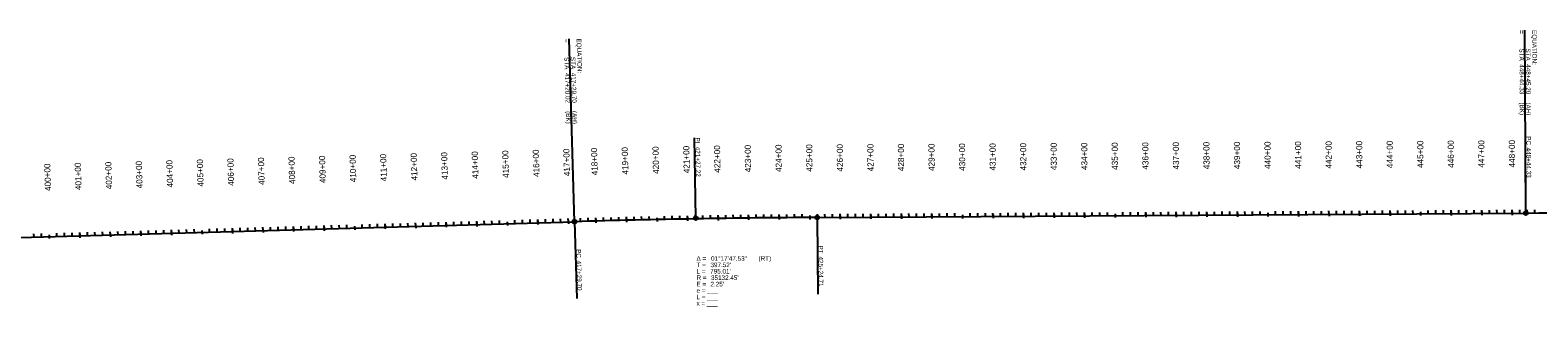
# Model space of a CAD drawing. Extents: x 22693007 to 22771804, y 6223023 to 6251673.
# Drawn here: x 22717627 to 22722562, y 6235486 to 6236393 of the extents above; entities that cross this region are included whole.
import ezdxf

# ---------------------------------------------------------------- set-up
doc = ezdxf.new("R2010")
doc.units = 0
for name, color, linetype in [('Default', 7, 'Continuous'), ('Draft_2', 7, 'Continuous'), ('NamedBoundary', 7, 'Continuous'), ('SheetBorder', 7, 'Continuous'), ('TextAlignment', 7, 'Continuous')]:
    doc.layers.add(name, color=color, linetype=linetype)

msp = doc.modelspace()

# ---------------------------------------------------------------- linework, layer by layer
at = {"layer": 'Default'}
for p, q in [((22720203.3, 6235778.9), (22722522.9, 6235793)), ((22714843.8, 6235633.8), (22719408.5, 6235765)), ((22714843.8, 6235633.8), (22719408.5, 6235765))]:
    msp.add_line(p, q, dxfattribs=at)
for centre, radius, start, end in [((22722417.6, 6253010.9), 17218.1, 270.3503, 272.59113), ((22720418.1, 6200647.1), 35132.4, 90.3503, 91.64684)]:
    msp.add_arc(centre, radius, start, end, dxfattribs=at)
at = {"layer": 'Draft_2'}
for p, q in [((22720778.6, 6235782.4), (22720778.5, 6235793.3)), ((22720878.6, 6235783), (22720878.5, 6235793.9)), ((22720978.6, 6235783.6), (22720978.5, 6235794.5)), ((22721078.6, 6235784.2), (22721078.5, 6235795.1)), ((22721278.6, 6235785.4), (22721278.5, 6235796.3)), ((22721378.6, 6235786), (22721378.5, 6235797)), ((22721478.6, 6235786.6), (22721478.5, 6235797.6)), ((22721578.6, 6235787.3), (22721578.5, 6235798.2)), ((22721678.6, 6235794), (22721678.6, 6235781.8)), ((22721778.6, 6235788.5), (22721778.5, 6235799.4)), ((22721878.6, 6235789.1), (22721878.5, 6235800)), ((22721978.6, 6235789.7), (22721978.5, 6235800.6)), ((22722078.6, 6235790.3), (22722078.5, 6235801.2)), ((22722178.5, 6235797), (22722178.6, 6235784.8)), ((22722278.6, 6235791.5), (22722278.5, 6235802.5)), ((22722378.6, 6235792.2), (22722378.5, 6235803.1)), ((22722478.6, 6235792.8), (22722478.5, 6235803.7)), ((22718288.9, 6235732.8), (22718288.6, 6235743.7)), ((22718388.9, 6235735.7), (22718388.5, 6235746.6)), ((22718488.8, 6235738.6), (22718488.5, 6235749.5)), ((22718588.8, 6235741.4), (22718588.5, 6235752.3)), ((22718688.6, 6235750.4), (22718688.9, 6235738.2)), ((22718788.7, 6235747.2), (22718788.4, 6235758.1)), ((22718888.7, 6235750.1), (22718888.3, 6235761)), ((22718988.6, 6235752.9), (22718988.3, 6235763.8)), ((22719088.6, 6235755.8), (22719088.3, 6235766.7)), ((22719188.4, 6235764.8), (22719188.7, 6235752.6)), ((22719288.5, 6235761.5), (22719288.2, 6235772.5)), ((22719388.4, 6235764.4), (22719388.1, 6235775.3)), ((22719478.7, 6235766.9), (22719478.4, 6235777.9)), ((22719578.7, 6235769.5), (22719578.4, 6235780.4)), ((22719678.5, 6235777.8), (22719678.8, 6235765.6)), ((22719778.7, 6235773.7), (22719778.5, 6235784.6)), ((22719878.6, 6235775.4), (22719878.5, 6235786.3)), ((22719978.6, 6235776.8), (22719978.5, 6235787.7)), ((22720078.6, 6235777.9), (22720078.5, 6235788.8)), ((22720178.6, 6235784.8), (22720178.7, 6235772.6)), ((22720278.6, 6235779.3), (22720278.5, 6235790.2)), ((22720378.6, 6235779.9), (22720378.5, 6235790.8)), ((22720478.6, 6235780.5), (22720478.5, 6235791.5)), ((22720578.6, 6235781.1), (22720578.5, 6235792.1)), ((22720678.6, 6235787.9), (22720678.6, 6235775.6)), ((22721178.6, 6235790.9), (22721178.6, 6235778.7)), ((22717689, 6235721.7), (22717689.3, 6235709.4)), ((22717789.1, 6235718.4), (22717788.8, 6235729.4)), ((22717889.1, 6235721.3), (22717888.8, 6235732.2)), ((22717989, 6235724.2), (22717988.7, 6235735.1)), ((22718089, 6235727.1), (22718088.7, 6235738)), ((22718188.8, 6235736.1), (22718189.1, 6235723.8))]:
    msp.add_line(p, q, dxfattribs=at)
at = {"layer": 'NamedBoundary'}
for p, q in [((22720203.3, 6235778.9), (22722522.9, 6235793)), ((22714843.8, 6235633.8), (22719408.5, 6235765))]:
    msp.add_line(p, q, dxfattribs=at)
for centre, radius, start, end in [((22722417.6, 6253010.9), 17218.1, 270.3503, 272.59113), ((22720418.1, 6200647.1), 35132.4, 90.3503, 91.64684)]:
    msp.add_arc(centre, radius, start, end, dxfattribs=at)
at = {"layer": 'SheetBorder'}
for p, q in [((22720628.6, 6235781.5), (22720628.5, 6235792.4)), ((22720653.6, 6235781.6), (22720653.5, 6235792.5)), ((22720703.6, 6235781.9), (22720703.5, 6235792.8)), ((22720728.6, 6235782.1), (22720728.5, 6235793)), ((22720753.6, 6235782.2), (22720753.5, 6235793.1)), ((22720803.6, 6235782.5), (22720803.5, 6235793.4)), ((22720828.6, 6235782.7), (22720828.5, 6235793.6)), ((22720853.6, 6235782.8), (22720853.5, 6235793.7)), ((22720903.6, 6235783.1), (22720903.5, 6235794.1)), ((22720928.6, 6235783.3), (22720928.5, 6235794.2)), ((22720953.6, 6235783.4), (22720953.5, 6235794.4)), ((22721003.6, 6235783.7), (22721003.5, 6235794.7)), ((22721028.6, 6235783.9), (22721028.5, 6235794.8)), ((22721053.6, 6235784.1), (22721053.5, 6235795)), ((22721103.6, 6235784.4), (22721103.5, 6235795.3)), ((22721128.6, 6235784.5), (22721128.5, 6235795.4)), ((22721153.6, 6235784.7), (22721153.5, 6235795.6)), ((22721203.6, 6235785), (22721203.5, 6235795.9)), ((22721228.6, 6235785.1), (22721228.5, 6235796)), ((22721253.6, 6235785.3), (22721253.5, 6235796.2)), ((22721303.6, 6235785.6), (22721303.5, 6235796.5)), ((22721328.6, 6235785.7), (22721328.5, 6235796.7)), ((22721353.6, 6235785.9), (22721353.5, 6235796.8)), ((22721403.6, 6235786.2), (22721403.5, 6235797.1)), ((22721428.6, 6235786.3), (22721428.5, 6235797.3)), ((22721453.6, 6235786.5), (22721453.5, 6235797.4)), ((22721478.6, 6235792.8), (22721478.6, 6235780.5)), ((22721503.6, 6235786.8), (22721503.5, 6235797.7)), ((22721528.6, 6235787), (22721528.5, 6235797.9)), ((22721553.6, 6235787.1), (22721553.5, 6235798)), ((22721578.6, 6235793.4), (22721578.6, 6235781.1)), ((22721603.6, 6235787.4), (22721603.5, 6235798.3)), ((22721628.6, 6235787.6), (22721628.5, 6235798.5)), ((22721653.6, 6235787.7), (22721653.5, 6235798.6)), ((22721678.6, 6235794), (22721678.6, 6235781.8)), ((22721703.6, 6235788), (22721703.5, 6235798.9)), ((22721728.6, 6235788.2), (22721728.5, 6235799.1)), ((22721753.6, 6235788.3), (22721753.5, 6235799.2)), ((22721778.6, 6235794.6), (22721778.6, 6235782.4)), ((22721803.6, 6235788.6), (22721803.5, 6235799.6)), ((22721828.6, 6235788.8), (22721828.5, 6235799.7)), ((22721853.6, 6235788.9), (22721853.5, 6235799.9)), ((22721878.5, 6235795.2), (22721878.6, 6235783)), ((22721903.6, 6235789.2), (22721903.5, 6235800.2)), ((22721928.6, 6235789.4), (22721928.5, 6235800.3)), ((22721953.6, 6235789.6), (22721953.5, 6235800.5)), ((22721978.5, 6235795.8), (22721978.6, 6235783.6)), ((22722003.6, 6235789.9), (22722003.5, 6235800.8)), ((22722028.6, 6235790), (22722028.5, 6235800.9)), ((22722053.6, 6235790.2), (22722053.5, 6235801.1)), ((22722078.5, 6235796.4), (22722078.6, 6235784.2)), ((22722103.6, 6235790.5), (22722103.5, 6235801.4)), ((22722128.6, 6235790.6), (22722128.5, 6235801.5)), ((22722153.6, 6235790.8), (22722153.5, 6235801.7)), ((22722178.5, 6235797), (22722178.6, 6235784.8)), ((22722203.6, 6235791.1), (22722203.5, 6235802)), ((22722228.6, 6235791.2), (22722228.5, 6235802.2)), ((22722253.6, 6235791.4), (22722253.5, 6235802.3)), ((22722278.5, 6235797.7), (22722278.6, 6235785.4)), ((22722303.6, 6235791.7), (22722303.5, 6235802.6)), ((22722328.6, 6235791.8), (22722328.5, 6235802.8)), ((22722353.6, 6235792), (22722353.5, 6235802.9)), ((22722378.5, 6235798.3), (22722378.6, 6235786)), ((22722403.6, 6235792.3), (22722403.5, 6235803.2)), ((22722428.6, 6235792.5), (22722428.5, 6235803.4)), ((22722453.6, 6235792.6), (22722453.5, 6235803.5)), ((22722478.5, 6235798.9), (22722478.6, 6235786.6)), ((22722503.6, 6235792.9), (22722503.5, 6235803.8)), ((22722527.7, 6235793.1), (22722527.6, 6235804)), ((22722552.7, 6235793.2), (22722552.6, 6235804.2)), ((22718263.9, 6235732.1), (22718263.6, 6235743)), ((22718313.9, 6235733.5), (22718313.6, 6235744.4)), ((22718338.9, 6235734.2), (22718338.6, 6235745.2)), ((22718363.9, 6235735), (22718363.6, 6235745.9)), ((22718413.8, 6235736.4), (22718413.5, 6235747.3)), ((22718438.8, 6235737.1), (22718438.5, 6235748)), ((22718463.8, 6235737.8), (22718463.5, 6235748.8)), ((22718488.6, 6235744.7), (22718489, 6235732.4)), ((22718513.8, 6235739.3), (22718513.5, 6235750.2)), ((22718538.8, 6235740), (22718538.5, 6235750.9)), ((22718563.8, 6235740.7), (22718563.5, 6235751.6)), ((22718588.6, 6235747.5), (22718589, 6235735.3)), ((22718613.8, 6235742.1), (22718613.5, 6235753.1)), ((22718638.8, 6235742.9), (22718638.4, 6235753.8)), ((22718663.7, 6235743.6), (22718663.4, 6235754.5)), ((22718688.6, 6235750.4), (22718688.9, 6235738.2)), ((22718713.7, 6235745), (22718713.4, 6235755.9)), ((22718738.7, 6235745.7), (22718738.4, 6235756.7)), ((22718763.7, 6235746.5), (22718763.4, 6235757.4)), ((22718788.5, 6235753.3), (22718788.9, 6235741.1)), ((22718813.7, 6235747.9), (22718813.4, 6235758.8)), ((22718838.7, 6235748.6), (22718838.4, 6235759.5)), ((22718863.7, 6235749.3), (22718863.3, 6235760.2)), ((22718888.5, 6235756.2), (22718888.8, 6235743.9)), ((22718913.6, 6235750.8), (22718913.3, 6235761.7)), ((22718938.6, 6235751.5), (22718938.3, 6235762.4)), ((22718963.6, 6235752.2), (22718963.3, 6235763.1)), ((22718988.4, 6235759), (22718988.8, 6235746.8)), ((22719013.6, 6235753.6), (22719013.3, 6235764.6)), ((22719038.6, 6235754.4), (22719038.3, 6235765.3)), ((22719063.6, 6235755.1), (22719063.3, 6235766)), ((22719088.4, 6235761.9), (22719088.7, 6235749.7)), ((22719113.6, 6235756.5), (22719113.2, 6235767.4)), ((22719138.5, 6235757.2), (22719138.2, 6235768.2)), ((22719163.5, 6235758), (22719163.2, 6235768.9)), ((22719188.4, 6235764.8), (22719188.7, 6235752.6)), ((22719213.5, 6235759.4), (22719213.2, 6235770.3)), ((22719238.5, 6235760.1), (22719238.2, 6235771)), ((22719263.5, 6235760.8), (22719263.2, 6235771.7)), ((22719288.3, 6235767.7), (22719288.7, 6235755.4)), ((22719313.5, 6235762.3), (22719313.2, 6235773.2)), ((22719338.5, 6235763), (22719338.2, 6235773.9)), ((22719363.5, 6235763.7), (22719363.1, 6235774.6)), ((22719388.3, 6235770.5), (22719388.6, 6235758.3)), ((22719428.7, 6235765.6), (22719428.4, 6235776.5)), ((22719453.7, 6235766.3), (22719453.4, 6235777.2)), ((22719478.6, 6235773.1), (22719478.9, 6235760.8)), ((22719503.7, 6235767.6), (22719503.4, 6235778.5)), ((22719528.7, 6235768.2), (22719528.4, 6235779.2)), ((22719553.7, 6235768.9), (22719553.4, 6235779.8)), ((22719578.5, 6235775.6), (22719578.8, 6235763.4)), ((22719603.7, 6235770.1), (22719603.4, 6235781)), ((22719628.7, 6235770.6), (22719628.4, 6235781.6)), ((22719653.7, 6235771.2), (22719653.4, 6235782.1)), ((22719678.5, 6235777.8), (22719678.8, 6235765.6)), ((22719703.7, 6235772.2), (22719703.4, 6235783.2)), ((22719728.7, 6235772.7), (22719728.4, 6235783.7)), ((22719753.7, 6235773.2), (22719753.4, 6235784.1)), ((22719778.5, 6235779.8), (22719778.8, 6235767.6)), ((22719803.6, 6235774.1), (22719803.5, 6235785.1)), ((22719828.6, 6235774.6), (22719828.5, 6235785.5)), ((22719853.6, 6235775), (22719853.5, 6235785.9)), ((22719878.5, 6235781.5), (22719878.7, 6235769.2)), ((22719903.6, 6235775.7), (22719903.5, 6235786.7)), ((22719928.6, 6235776.1), (22719928.5, 6235787)), ((22719953.6, 6235776.4), (22719953.5, 6235787.4)), ((22719978.6, 6235782.9), (22719978.7, 6235770.6)), ((22720003.6, 6235777.1), (22720003.5, 6235788)), ((22720028.6, 6235777.3), (22720028.5, 6235788.3)), ((22720053.6, 6235777.6), (22720053.5, 6235788.5)), ((22720078.6, 6235784), (22720078.7, 6235771.7)), ((22720103.6, 6235778.1), (22720103.5, 6235789)), ((22720128.6, 6235778.3), (22720128.5, 6235789.2)), ((22720153.6, 6235778.5), (22720153.5, 6235789.4)), ((22720178.6, 6235784.8), (22720178.7, 6235772.6)), ((22720203.6, 6235778.9), (22720203.6, 6235789.8)), ((22720228.6, 6235779), (22720228.5, 6235789.9)), ((22720253.6, 6235779.2), (22720253.5, 6235790.1)), ((22720278.6, 6235785.4), (22720278.7, 6235773.2)), ((22720303.6, 6235779.5), (22720303.5, 6235790.4)), ((22720328.6, 6235779.6), (22720328.5, 6235790.5)), ((22720353.6, 6235779.8), (22720353.5, 6235790.7)), ((22720378.6, 6235786), (22720378.7, 6235773.8)), ((22720403.6, 6235780.1), (22720403.5, 6235791)), ((22720428.6, 6235780.2), (22720428.5, 6235791.1)), ((22720453.6, 6235780.4), (22720453.5, 6235791.3)), ((22720478.6, 6235786.7), (22720478.6, 6235774.4)), ((22720503.6, 6235780.7), (22720503.5, 6235791.6)), ((22720528.6, 6235780.8), (22720528.5, 6235791.8)), ((22720553.6, 6235781), (22720553.5, 6235791.9)), ((22720578.6, 6235787.3), (22720578.6, 6235775)), ((22720603.6, 6235781.3), (22720603.5, 6235792.2)), ((22720678.6, 6235787.9), (22720678.6, 6235775.6)), ((22720778.6, 6235788.5), (22720778.6, 6235776.2)), ((22720878.6, 6235789.1), (22720878.6, 6235776.9)), ((22720978.6, 6235789.7), (22720978.6, 6235777.5)), ((22721078.6, 6235790.3), (22721078.6, 6235778.1)), ((22721178.6, 6235790.9), (22721178.6, 6235778.7)), ((22721278.6, 6235791.5), (22721278.6, 6235779.3)), ((22721378.6, 6235792.2), (22721378.6, 6235779.9)), ((22717639.2, 6235714.1), (22717638.9, 6235725)), ((22717664.2, 6235714.8), (22717663.8, 6235725.8)), ((22717689, 6235721.7), (22717689.3, 6235709.4)), ((22717714.1, 6235716.3), (22717713.8, 6235727.2)), ((22717739.1, 6235717), (22717738.8, 6235727.9)), ((22717764.1, 6235717.7), (22717763.8, 6235728.6)), ((22717788.9, 6235724.6), (22717789.3, 6235712.3)), ((22717814.1, 6235719.2), (22717813.8, 6235730.1)), ((22717839.1, 6235719.9), (22717838.8, 6235730.8)), ((22717864.1, 6235720.6), (22717863.8, 6235731.5)), ((22717888.9, 6235727.4), (22717889.2, 6235715.2)), ((22717914.1, 6235722), (22717913.7, 6235732.9)), ((22717939, 6235722.8), (22717938.7, 6235733.7)), ((22717964, 6235723.5), (22717963.7, 6235734.4)), ((22717988.8, 6235730.3), (22717989.2, 6235718.1)), ((22718014, 6235724.9), (22718013.7, 6235735.8)), ((22718039, 6235725.6), (22718038.7, 6235736.5)), ((22718064, 6235726.3), (22718063.7, 6235737.3)), ((22718088.8, 6235733.2), (22718089.2, 6235720.9)), ((22718114, 6235727.8), (22718113.7, 6235738.7)), ((22718139, 6235728.5), (22718138.6, 6235739.4)), ((22718164, 6235729.2), (22718163.6, 6235740.1)), ((22718188.8, 6235736.1), (22718189.1, 6235723.8)), ((22718213.9, 6235730.7), (22718213.6, 6235741.6)), ((22718238.9, 6235731.4), (22718238.6, 6235742.3)), ((22718288.7, 6235738.9), (22718289.1, 6235726.7)), ((22718388.7, 6235741.8), (22718389, 6235729.6))]:
    msp.add_line(p, q, dxfattribs=at)
at = {"layer": 'TextAlignment'}
for p, q in [((22722522.9, 6235793), (22722519.2, 6236393)), ((22722519.2, 6236393), (22722519.2, 6236393)), ((22719408.5, 6235765), (22719391.2, 6236364.7)), ((22719391.2, 6236364.7), (22719391.2, 6236364.7)), ((22719805.8, 6235776.4), (22719801.2, 6236040.4)), ((22719801.2, 6236040.4), (22719801.2, 6236040.4)), ((22722522.9, 6235793), (22722521.4, 6236045)), ((22722521.4, 6236045), (22722521.4, 6236045)), ((22719408.5, 6235765), (22719415.7, 6235513.1)), ((22720203.3, 6235778.9), (22720204.9, 6235526.9)), ((22719415.7, 6235513.1), (22719415.7, 6235513.1)), ((22720204.9, 6235526.9), (22720204.9, 6235526.9))]:
    msp.add_line(p, q, dxfattribs=at)
for centre, radius in [((22722522.9, 6235793), 6.24), ((22722522.9, 6235793), 5.34), ((22719408.5, 6235765), 6.24), ((22719408.5, 6235765), 5.34), ((22719805.8, 6235776.4), 6.24), ((22720203.3, 6235778.9), 6.24)]:
    msp.add_circle(centre, radius, dxfattribs=at)

# ---------------------------------------------------------------- texts
at = {"layer": 'Draft_2'}
for s, rotation, p in [('415+00', 91.6468, (22719194.2, 6235908.9)), ('420+00', 91.206, (22719685.5, 6235921.9)), ('425+00', 90.3906, (22720187.6, 6235928.8)), ('430+00', 90.3503, (22720687.7, 6235931.8)), ('435+00', 90.3503, (22721187.7, 6235934.9)), ('440+00', 90.3503, (22721687.7, 6235937.9)), ('445+00', 90.3503, (22722187.7, 6235941)), ('400+00', 91.6468, (22717694.9, 6235865.8)), ('405+00', 91.6468, (22718194.6, 6235880.2)), ('410+00', 91.6468, (22718694.4, 6235894.5))]:
    msp.add_text(s, height=20.04, rotation=rotation, dxfattribs=at).set_placement(p)
at = {"layer": 'SheetBorder'}
for s, rotation, p in [('413+00', 91.6468, (22718994.3, 6235903.2)), ('414+00', 91.6468, (22719094.3, 6235906)), ('415+00', 91.6468, (22719194.2, 6235908.9)), ('416+00', 91.6468, (22719294.2, 6235911.8)), ('417+00', 91.6468, (22719394.2, 6235914.6)), ('418+00', 91.5322, (22719484.7, 6235917.2)), ('419+00', 91.3691, (22719585.1, 6235919.7)), ('420+00', 91.206, (22719685.5, 6235921.9)), ('421+00', 91.0429, (22719785.9, 6235923.8)), ('422+00', 90.8798, (22719886.4, 6235925.5)), ('423+00', 90.7168, (22719986.8, 6235926.9)), ('424+00', 90.5537, (22720087.2, 6235928)), ('425+00', 90.3906, (22720187.6, 6235928.8)), ('426+00', 90.3503, (22720287.7, 6235929.4)), ('427+00', 90.3503, (22720387.7, 6235930)), ('428+00', 90.3503, (22720487.7, 6235930.6)), ('429+00', 90.3503, (22720587.7, 6235931.2)), ('430+00', 90.3503, (22720687.7, 6235931.8)), ('431+00', 90.3503, (22720787.7, 6235932.4)), ('432+00', 90.3503, (22720887.7, 6235933)), ('433+00', 90.3503, (22720987.7, 6235933.7)), ('434+00', 90.3503, (22721087.7, 6235934.3)), ('435+00', 90.3503, (22721187.7, 6235934.9)), ('436+00', 90.3503, (22721287.7, 6235935.5)), ('437+00', 90.3503, (22721387.7, 6235936.1)), ('438+00', 90.3503, (22721487.7, 6235936.7)), ('439+00', 90.3503, (22721587.7, 6235937.3)), ('440+00', 90.3503, (22721687.7, 6235937.9)), ('441+00', 90.3503, (22721787.7, 6235938.5)), ('442+00', 90.3503, (22721887.7, 6235939.2)), ('443+00', 90.3503, (22721987.7, 6235939.8)), ('444+00', 90.3503, (22722087.7, 6235940.4)), ('445+00', 90.3503, (22722187.7, 6235941)), ('446+00', 90.3503, (22722287.7, 6235941.6)), ('447+00', 90.3503, (22722387.7, 6235942.2)), ('448+00', 90.3503, (22722487.7, 6235942.8)), ('400+00', 91.6468, (22717694.9, 6235865.8)), ('401+00', 91.6468, (22717794.8, 6235868.7)), ('402+00', 91.6468, (22717894.8, 6235871.5)), ('403+00', 91.6468, (22717994.7, 6235874.4)), ('404+00', 91.6468, (22718094.7, 6235877.3)), ('405+00', 91.6468, (22718194.6, 6235880.2)), ('406+00', 91.6468, (22718294.6, 6235883)), ('407+00', 91.6468, (22718394.6, 6235885.9)), ('408+00', 91.6468, (22718494.5, 6235888.8)), ('409+00', 91.6468, (22718594.5, 6235891.7)), ('410+00', 91.6468, (22718694.4, 6235894.5)), ('411+00', 91.6468, (22718794.4, 6235897.4)), ('412+00', 91.6468, (22718894.4, 6235900.3))]:
    msp.add_text(s, height=20.04, rotation=rotation, dxfattribs=at).set_placement(p)
at = {"layer": 'TextAlignment'}
for s, rotation, p in [('=', 270.3503, (22722501.6, 6236392.9)), ('EQUATION:', 270.3503, (22722543.5, 6236393.2)), ('=', 271.6468, (22719373.5, 6236364.2)), ('EQUATION:', 271.6468, (22719415.5, 6236365.4)), ('STA ', 271.6468, (22719375.3, 6236304.3)), ('STA ', 271.6468, (22719396.2, 6236304.9)), ('STA ', 270.3503, (22722501.9, 6236332.9)), ('STA ', 270.3503, (22722522.9, 6236333)), ('417+20.02', 271.6468, (22719376.8, 6236252.3)), ('417+29.70', 271.6468, (22719397.7, 6236252.9)), ('448+44.33', 270.3503, (22722502.2, 6236281)), ('448+45.20', 270.3503, (22722523.2, 6236281.1)), ('(BK)', 270.3503, (22722503, 6236155.7)), ('(AH)', 270.3503, (22722524, 6236155.8)), ('(BK)', 271.6468, (22719380.4, 6236127.1)), ('(AH)', 271.6468, (22719401.3, 6236127.7)), ('PI ', 270.9986, (22719804.2, 6236040.4)), ('PC', 270.3503, (22722524.7, 6236045)), ('421+27.22', 270.9986, (22719804.7, 6236010.5)), ('448+44.33', 270.3503, (22722524.9, 6236007.7)), ('PC', 271.6468, (22719414.3, 6235674.8)), ('PT', 270.3503, (22720207.2, 6235687.1)), ('425+24.71', 270.3503, (22720207.4, 6235650.8)), ('417+29.70', 271.6468, (22719415.4, 6235637.5))]:
    msp.add_text(s, height=15, rotation=rotation, dxfattribs=at).set_placement(p)
for s, p in [('Δ = ', (22719808, 6235636.9)), ('01°17\'47.53"', (22719855.5, 6235636.9)), (' (RT)', (22720005.2, 6235636.9)), ('T = ', (22719808, 6235615.9)), ('L = ', (22719808, 6235594.9)), ("795.01'", (22719852.7, 6235594.9)), ("397.52'", (22719853.6, 6235615.9)), ('R = ', (22719808, 6235573.9)), ('E = ', (22719808, 6235552.9)), ("2.25'", (22719853.6, 6235552.9)), ("35132.45'", (22719855.4, 6235573.9)), ('x = ___', (22719808, 6235489.9)), ('e = ___ ', (22719808, 6235531.9)), ('L = ___', (22719808, 6235510.9))]:
    msp.add_text(s, height=15, dxfattribs=at).set_placement(p)

doc.saveas('drawing.dxf')
